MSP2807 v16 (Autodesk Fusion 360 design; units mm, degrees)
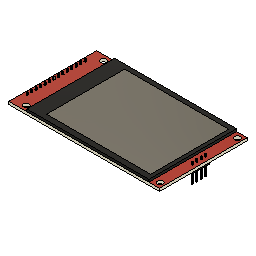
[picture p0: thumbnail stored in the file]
sketch "スケッチ1" plane through (0, 0, 0) normal (0, 1, 0) x axis (1, 0, 0)
  line L1 (85.8, 0) -> (0, 0)
  line L2 (85.8, -50) -> (85.8, 0)
  line L3 (0, -50) -> (85.8, -50)
  line L4 (0, 0) -> (0, -50)
  line L5 (2, 0) -> (0, 0)
  line L6 (2, -50) -> (2, 0)
  line L7 (0, -50) -> (2, -50)
  line L8 (0, 0) -> (0, -50)
  line L9 (2, 0) -> (0, 0)
  line L10 (2, -8.49) -> (2, 0)
  line L11 (0, -8.49) -> (2, -8.49)
  line L12 (0, 0) -> (0, -8.49)
  line L13 (0, -11.03) -> (2, -11.03)
  line L14 (0, -13.57) -> (2, -13.57)
  line L15 (0, -16.11) -> (2, -16.11)
  line L16 (0, -18.65) -> (2, -18.65)
  line L17 (0, -28.81) -> (2, -28.81)
  line L18 (0, -26.27) -> (2, -26.27)
  line L19 (0, -23.73) -> (2, -23.73)
  line L20 (0, -21.19) -> (2, -21.19)
  line L21 (0, -31.35) -> (2, -31.35)
  line L22 (0, -33.89) -> (2, -33.89)
  line L23 (0, -36.43) -> (2, -36.43)
  line L24 (0, -38.97) -> (2, -38.97)
  line L25 (0, -41.51) -> (2, -41.51)
  line L26 (10.3, 0) -> (2, 0)
  line L27 (10.3, -50) -> (10.3, 0)
  line L28 (2, -50) -> (10.3, -50)
  line L29 (2, 0) -> (2, -50)
  line L30 (79.8, 0) -> (2, 0)
  line L31 (79.8, -50) -> (79.8, 0)
  line L32 (2, -50) -> (79.8, -50)
  line L33 (2, 0) -> (2, -50)
  line L34 (18.5, 0) -> (2, 0)
  line L35 (18.5, -2.5) -> (18.5, 0)
  line L36 (2, -2.5) -> (18.5, -2.5)
  line L37 (2, 0) -> (2, -2.5)
  line L38 (77.8, 0) -> (2, 0)
  line L39 (77.8, -46.99) -> (77.8, 0)
  line L40 (2, -46.99) -> (77.8, -46.99)
  line L41 (2, 0) -> (2, -46.99)
  line L42 (77.8, -2.5) -> (18.5, -2.5)
  line L43 (77.8, -46.99) -> (77.8, -2.5)
  line L44 (18.5, -46.99) -> (77.8, -46.99)
  line L45 (18.5, -2.5) -> (18.5, -46.99)
  line L46 (83.28, 0) -> (2, 0)
  line L47 (83.28, -21.19) -> (83.28, 0)
  line L48 (2, -21.19) -> (83.28, -21.19)
  line L49 (2, 0) -> (2, -21.19)
  line L50 (81.28, -21.19) -> (83.28, -21.19)
  line L51 (81.28, -23.73) -> (83.28, -23.73)
  line L52 (81.28, -26.27) -> (83.28, -26.27)
  line L53 (81.28, -28.81) -> (83.28, -28.81)
  line L54 (7, 0) -> (0, 0)
  line L55 (7, -3) -> (7, 0)
  line L56 (0, -3) -> (7, -3)
  line L57 (0, 0) -> (0, -3)
  line L58 (7, -50) -> (0, -50)
  line L59 (7, -47) -> (7, -50)
  line L60 (0, -47) -> (7, -47)
  line L61 (0, -50) -> (0, -47)
  line L62 (83.3, -47) -> (7, -47)
  line L63 (83.3, -3) -> (7, -3)
  line L64 (83.3, 0) -> (83.3, -3)
  line L65 (7, 0) -> (83.3, 0)
  line L66 (7, -3) -> (7, 0)
  line L67 (1.7, -8.49) -> (2, -8.49)
  line L68 (1.7, -8.19) -> (1.7, -8.49)
  line L69 (2, -8.19) -> (1.7, -8.19)
  line L70 (2, -8.49) -> (2, -8.19)
  line L71 (2.3, -8.19) -> (1.7, -8.19)
  line L72 (2.3, -8.79) -> (2.3, -8.19)
  line L73 (1.7, -8.79) -> (2.3, -8.79)
  line L74 (1.7, -8.19) -> (1.7, -8.79)
  line L75 (2.3, -10.73) -> (1.7, -10.73)
  line L76 (2.3, -11.33) -> (2.3, -10.73)
  line L77 (1.7, -11.33) -> (2.3, -11.33)
  line L78 (1.7, -10.73) -> (1.7, -11.33)
  line L79 (2.3, -13.27) -> (1.7, -13.27)
  line L80 (2.3, -13.87) -> (2.3, -13.27)
  line L81 (1.7, -13.27) -> (1.7, -13.87)
  line L82 (1.7, -13.87) -> (2.3, -13.87)
  line L83 (2.3, -15.81) -> (1.7, -15.81)
  line L84 (1.7, -15.81) -> (1.7, -16.41)
  line L85 (1.7, -16.41) -> (2.3, -16.41)
  line L86 (2.3, -16.41) -> (2.3, -15.81)
  line L87 (2, -18.35) -> (1.7, -18.35)
  line L88 (2.3, -18.35) -> (1.7, -18.35)
  line L89 (2.3, -18.95) -> (2.3, -18.35)
  line L90 (1.7, -18.95) -> (2.3, -18.95)
  line L91 (1.7, -18.35) -> (1.7, -18.95)
  line L92 (2.3, -20.89) -> (1.7, -20.89)
  line L93 (1.7, -20.89) -> (1.7, -21.49)
  line L94 (1.7, -21.49) -> (2.3, -21.49)
  line L95 (2.3, -21.49) -> (2.3, -20.89)
  line L96 (2.3, -23.43) -> (1.7, -23.43)
  line L97 (2.3, -24.03) -> (2.3, -23.43)
  line L98 (1.7, -24.03) -> (2.3, -24.03)
  line L99 (1.7, -23.43) -> (1.7, -24.03)
  line L100 (2.3, -26.57) -> (2.3, -25.97)
  line L101 (2.3, -25.97) -> (1.7, -25.97)
  line L102 (1.7, -25.97) -> (1.7, -26.57)
  line L103 (1.7, -26.57) -> (2.3, -26.57)
  line L104 (1.7, -41.81) -> (2.3, -41.81)
  line L105 (1.7, -41.21) -> (1.7, -41.81)
  line L106 (2.3, -41.21) -> (1.7, -41.21)
  line L107 (2.3, -41.81) -> (2.3, -41.21)
  line L108 (1.7, -39.27) -> (2.3, -39.27)
  line L109 (2.3, -39.27) -> (2.3, -38.67)
  line L110 (2.3, -38.67) -> (1.7, -38.67)
  line L111 (1.7, -38.67) -> (1.7, -39.27)
  line L112 (1.7, -36.73) -> (2.3, -36.73)
  line L113 (2.3, -36.73) -> (2.3, -36.13)
  line L114 (2.3, -36.13) -> (1.7, -36.13)
  line L115 (1.7, -36.13) -> (1.7, -36.73)
  line L116 (1.7, -34.19) -> (2.3, -34.19)
  line L117 (1.7, -33.59) -> (1.7, -34.19)
  line L118 (2.3, -34.19) -> (2.3, -33.59)
  line L119 (2.3, -33.59) -> (1.7, -33.59)
  line L120 (2.3, -31.05) -> (1.7, -31.05)
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  point P1 (0, 0)
  point P2 (0, 0)
  point P8 (2, -50)
  point P6 (0, 0)
  point P10 (0, 0)
  point P12 (2, -8.49)
  point P14 (2, -8.49)
  point P83 (0, 0)
  point P88 (7, -47)
  point P90 (7, -47)
  point P85 (7, -3)
  point P91 (7, -3)
  point P92 (7, -47)
  point P93 (83.3, -47)
  point P94 (83.3, -47)
  point P95 (7, -3)
  point P96 (83.3, -3)
  point P99 (83.3, -3)
  point P100 (2, -8.49)
  point P3 (85.8, 0)
  point P5 (0, -50)
  point P7 (2, 0)
  point P11 (2, 0)
  point P13 (0, -8.49)
  point P54 (10.3, 0)
  point P57 (79.8, 0)
  point P60 (18.5, 0)
  point P62 (2, -2.5)
  point P63 (77.8, 0)
  point P65 (2, -46.99)
  point P68 (83.28, 0)
  point P70 (2, -21.19)
  point P84 (7, 0)
  point P86 (0, -3)
  point P87 (7, -50)
  point P89 (0, -47)
  point P101 (1.7, -8.49)
  point P103 (2, -8.19)
  point P102 (1.7, -8.19)
  point P104 (2.3, -8.19)
  point P106 (1.7, -8.79)
  point P108 (2.3, -10.73)
  point P110 (1.7, -10.73)
  point P107 (1.7, -11.33)
  point P116 (2.3, -13.27)
  point P118 (1.7, -13.27)
  point P113 (1.7, -13.87)
  point P111 (1.7, -15.81)
  point P115 (2.3, -15.81)
  point P114 (1.7, -16.41)
  point P126 (2.3, -18.35)
  point P135 (1.7, -18.35)
  point P123 (1.7, -18.95)
  point P119 (1.7, -20.89)
  point P125 (2.3, -20.89)
  point P124 (1.7, -21.49)
  point P122 (1.7, -23.43)
  point P133 (2.3, -23.43)
  point P131 (1.7, -24.03)
  point P128 (1.7, -25.97)
  point P132 (2.3, -25.97)
  point P130 (1.7, -26.57)
  point P137 (1.7, -28.51)
  point P143 (2.3, -28.51)
  point P141 (1.7, -29.11)
  point P138 (1.7, -31.05)
  point P142 (2.3, -31.05)
  point P140 (1.7, -31.65)
  point P146 (1.7, -33.59)
  point P150 (2.3, -33.59)
  point P158 (1.7, -34.19)
  point P147 (2.3, -36.13)
  point P159 (1.7, -36.13)
  point P149 (1.7, -36.73)
  point P145 (2.3, -38.67)
  point P148 (1.7, -38.67)
  point P153 (1.7, -39.27)
  point P144 (2.3, -41.21)
  point P156 (1.7, -41.21)
  point P152 (1.7, -41.81)
  point P166 (83.58, -20.89)
  point P175 (82.98, -20.89)
  point P168 (82.98, -21.49)
  point P165 (83.58, -23.43)
  point P167 (82.98, -23.43)
  point P170 (82.98, -24.03)
  point P164 (83.58, -25.97)
  point P173 (82.98, -25.97)
  point P169 (82.98, -26.57)
  point P160 (82.98, -28.51)
  point P161 (83.58, -28.51)
  point P163 (82.98, -29.11)
  horizontal L1
  vertical L2
  horizontal L3
  vertical L4
  coincident P1 P2
  horizontal L5
  vertical L6
  horizontal L7
  vertical L8
  coincident L3 P8
  coincident P1 P6
  horizontal L9
  vertical L10
  horizontal L11
  vertical L12
  coincident P1 P10
  coincident P12 P14
  horizontal L13
  horizontal L14
  horizontal L15
  horizontal L16
  horizontal L20
  horizontal L19
  horizontal L18
  horizontal L17
  horizontal L21
  horizontal L22
  horizontal L23
  horizontal L24
  horizontal L25
  horizontal L26
  vertical L27
  horizontal L28
  vertical L29
  horizontal L30
  vertical L31
  horizontal L32
  vertical L33
  horizontal L34
  vertical L35
  horizontal L36
  vertical L37
  horizontal L38
  vertical L39
  horizontal L40
  vertical L41
  horizontal L42
  vertical L43
  horizontal L44
  vertical L45
  horizontal L46
  vertical L47
  horizontal L48
  vertical L49
  horizontal L50
  horizontal L51
  horizontal L52
  horizontal L53
  horizontal L54
  vertical L55
  horizontal L56
  vertical L57
  coincident P1 P83
  horizontal L58
  vertical L59
  horizontal L60
  vertical L61
  coincident P88 P90
  coincident P85 P91
  horizontal L62
  coincident P90 P92
  coincident P93 P94
  horizontal L63
  vertical L64
  horizontal L65
  vertical L66
  coincident P91 P95
  coincident P96 P99
  horizontal L67
  vertical L68
  horizontal L69
  vertical L70
  coincident P14 P100
  horizontal L71
  vertical L72
  horizontal L73
  vertical L74
  horizontal L75
  vertical L76
  horizontal L77
  vertical L78
  horizontal L79
  vertical L80
  horizontal L82
  vertical L81
  horizontal L83
  vertical L86
  horizontal L85
  vertical L84
  horizontal L87
  horizontal L88
  vertical L89
  horizontal L90
  vertical L91
  horizontal L92
  vertical L95
  horizontal L94
  vertical L93
  horizontal L96
  vertical L97
  horizontal L98
  vertical L99
  horizontal L101
  vertical L100
  horizontal L103
  vertical L102
  horizontal L120
  horizontal L119
  vertical L118
  horizontal L116
  vertical L117
  horizontal L114
  vertical L113
  horizontal L112
  vertical L115
  horizontal L110
  vertical L109
  horizontal L108
  vertical L111
  horizontal L106
  vertical L107
  horizontal L104
  vertical L105
  dimension "d1" distance P2 P3 = 85.8
  dimension "d2" distance P2 P5 = 50
  dimension "d3" distance P6 P7 = 2
  dimension "d4" distance P10 P11 = 2
  dimension "d5" distance P10 P13 = 8.49
  dimension "d6" diameter = 1
  dimension "d7" diameter = 1
  dimension "d8" diameter = 1
  dimension "d9" diameter = 1
  dimension "d10" diameter = 1
  dimension "d11" diameter = 1
  dimension "d12" diameter = 1
  dimension "d13" diameter = 1
  dimension "d14" diameter = 1
  dimension "d15" diameter = 1
  dimension "d16" diameter = 1
  dimension "d17" diameter = 1
  dimension "d18" diameter = 1
  dimension "d19" diameter = 1
  dimension "d20" distance P7 P54 = 8.3
  dimension "d21" distance P7 P57 = 77.8
  dimension "d22" distance P7 P60 = 16.5
  dimension "d23" distance P7 P62 = 2.5
  dimension "d24" distance P7 P63 = 75.8
  dimension "d25" distance P7 P65 = 46.99
  dimension "d30" distance P7 P68 = 81.28
  dimension "d31" distance P7 P70 = 21.19
  dimension "d32" diameter = 1
  dimension "d33" diameter = 1
  dimension "d34" diameter = 1
  dimension "d35" diameter = 1
  dimension "d36" distance P83 P84 = 7
  dimension "d37" distance P83 P86 = 3
  dimension "d38" distance P5 P87 = 7
  dimension "d39" distance P5 P89 = 3
  dimension "d40" diameter = 3.2
  dimension "d41" diameter = 3.2
  dimension "d42" distance P92 P93 = 76.3 (= "73.1 mm + 3.2 mm")
  dimension "d44" diameter = 3.2
  dimension "d45" distance P95 P96 = 76.3
  dimension "d46" diameter = 3.2
  dimension "d49" distance P100 P101 = 0.3
  dimension "d50" distance P100 P103 = 0.3
  dimension "d51" distance P102 P104 = 0.6
  dimension "d52" distance P102 P106 = 0.6
  dimension "d53" distance P108 P110 = 0.6
  dimension "d54" distance P107 P110 = 0.6
  dimension "d55" distance P116 P118 = 0.6
  dimension "d56" distance P113 P118 = 0.6
  dimension "d57" distance P111 P115 = 0.6
  dimension "d58" distance P111 P114 = 0.6
  dimension "d59" distance P126 P135 = 0.6
  dimension "d60" distance P123 P135 = 0.6
  dimension "d61" distance P119 P125 = 0.6
  dimension "d62" distance P119 P124 = 0.6
  dimension "d63" distance P122 P133 = 0.6
  dimension "d64" distance P122 P131 = 0.6
  dimension "d65" distance P128 P132 = 0.6
  dimension "d66" distance P128 P130 = 0.6
  dimension "d67" distance P137 P143 = 0.6
  dimension "d68" distance P137 P141 = 0.6
  dimension "d69" distance P138 P142 = 0.6
  dimension "d70" distance P138 P140 = 0.6
  dimension "d71" distance P146 P150 = 0.6
  dimension "d72" distance P146 P158 = 0.6
  dimension "d73" distance P147 P159 = 0.6
  dimension "d74" distance P149 P159 = 0.6
  dimension "d75" distance P145 P148 = 0.6
  dimension "d76" distance P148 P153 = 0.6
  dimension "d77" distance P144 P156 = 0.6
  dimension "d78" distance P152 P156 = 0.6
  dimension "d79" distance P166 P175 = 0.6
  dimension "d80" distance P168 P175 = 0.6
  dimension "d81" distance P165 P167 = 0.6
  dimension "d82" distance P167 P170 = 0.6
  dimension "d83" distance P164 P173 = 0.6
  dimension "d84" distance P169 P173 = 0.6
  dimension "d85" distance P160 P161 = 0.6
  dimension "d86" distance P160 P163 = 0.6
extrude "押し出し1" new body sketch "スケッチ1" profile of L39 L40 L42 L43 L44 L45 along normal blind 1.4
sketch "スケッチ2" plane through (0, 0, 0) normal (0, 1, 0) x axis (1, 0, 0)
extrude "押し出し2" new body sketch "スケッチ1" profile of L1 L3 L27 L30 L31 L32 L34 L35 L36 L38 L39 L40 L42 L43 L44 L45 along normal blind 1.4
extrude "押し出し3" new body sketch "スケッチ1" against normal blind 1.6
extrude "押し出し4" new body sketch "スケッチ1" against normal blind 9.8
extrude "押し出し5" add of existing geometry blind 1.4
sketch "スケッチ3" plane through (0, -1.6, 0) normal (0, -1, 0) x axis (1, 0, 0)
  line L1 (85.8, 0) -> (0, 0)
  line L2 (85.8, 50) -> (85.8, 0)
  line L3 (0, 50) -> (85.8, 50)
  line L4 (0, 0) -> (0, 50)
  line L5 (3.24, 41.81) -> (2.3, 41.81)
  line L6 (3.24, 42.75) -> (3.24, 41.81)
  line L7 (2.3, 42.75) -> (3.24, 42.75)
  line L8 (2.3, 41.81) -> (2.3, 42.75)
  line L9 (0.76, 41.81) -> (1.7, 41.81)
  line L10 (0.76, 42.75) -> (0.76, 41.81)
  line L11 (1.7, 42.75) -> (0.76, 42.75)
  line L12 (1.7, 41.81) -> (1.7, 42.75)
  line L13 (0.76, 8.19) -> (1.7, 8.19)
  line L14 (0.76, 7.25) -> (0.76, 8.19)
  line L15 (1.7, 7.25) -> (0.76, 7.25)
  line L16 (1.7, 8.19) -> (1.7, 7.25)
  line L17 (3.24, 7.25) -> (0.76, 7.25)
  line L18 (3.24, 42.75) -> (3.24, 7.25)
  line L19 (0.76, 42.75) -> (3.24, 42.75)
  line L20 (0.76, 7.25) -> (0.76, 42.75)
  line L21 (2.3, 41.81) -> (1.7, 41.81)
  line L22 (2.3, 41.21) -> (2.3, 41.81)
  line L23 (1.7, 41.21) -> (2.3, 41.21)
  line L24 (1.7, 41.81) -> (1.7, 41.21)
  line L25 (84.52, 29.11) -> (83.58, 29.11)
  line L26 (84.52, 30.05) -> (84.52, 29.11)
  line L27 (83.58, 30.05) -> (84.52, 30.05)
  line L28 (83.58, 29.11) -> (83.58, 30.05)
  line L29 (82.04, 20.89) -> (82.98, 20.89)
  line L30 (82.04, 19.95) -> (82.04, 20.89)
  line L31 (82.98, 19.95) -> (82.04, 19.95)
  line L32 (82.98, 20.89) -> (82.98, 19.95)
  line L33 (84.52, 19.95) -> (82.04, 19.95)
  line L34 (84.52, 30.05) -> (84.52, 19.95)
  line L35 (82.04, 30.05) -> (84.52, 30.05)
  line L36 (82.04, 19.95) -> (82.04, 30.05)
  line L37 (2.3, 39.27) -> (1.7, 39.27)
  line L38 (2.3, 38.67) -> (2.3, 39.27)
  line L39 (1.7, 38.67) -> (2.3, 38.67)
  line L40 (1.7, 39.27) -> (1.7, 38.67)
  line L41 (2.3, 36.73) -> (1.7, 36.73)
  line L42 (2.3, 36.13) -> (2.3, 36.73)
  line L43 (1.7, 36.13) -> (2.3, 36.13)
  line L44 (1.7, 36.73) -> (1.7, 36.13)
  line L45 (2.3, 34.19) -> (1.7, 34.19)
  line L46 (2.3, 33.59) -> (2.3, 34.19)
  line L47 (1.7, 33.59) -> (2.3, 33.59)
  line L48 (1.7, 34.19) -> (1.7, 33.59)
  line L49 (2.3, 31.65) -> (1.7, 31.65)
  line L50 (2.3, 31.05) -> (2.3, 31.65)
  line L51 (1.7, 31.05) -> (2.3, 31.05)
  line L52 (1.7, 31.65) -> (1.7, 31.05)
  line L53 (2.3, 29.11) -> (1.7, 29.11)
  line L54 (2.3, 28.51) -> (2.3, 29.11)
  line L55 (1.7, 28.51) -> (2.3, 28.51)
  line L56 (1.7, 29.11) -> (1.7, 28.51)
  line L57 (2.3, 26.57) -> (1.7, 26.57)
  line L58 (2.3, 25.97) -> (2.3, 26.57)
  line L59 (1.7, 25.97) -> (2.3, 25.97)
  line L60 (1.7, 26.57) -> (1.7, 25.97)
  line L61 (2.3, 24.03) -> (1.7, 24.03)
  line L62 (2.3, 23.43) -> (2.3, 24.03)
  line L63 (1.7, 23.43) -> (2.3, 23.43)
  line L64 (1.7, 24.03) -> (1.7, 23.43)
  line L65 (2.3, 21.49) -> (1.7, 21.49)
  line L66 (2.3, 20.89) -> (2.3, 21.49)
  line L67 (1.7, 20.89) -> (2.3, 20.89)
  line L68 (1.7, 21.49) -> (1.7, 20.89)
  line L69 (2.3, 18.95) -> (1.7, 18.95)
  line L70 (2.3, 18.35) -> (2.3, 18.95)
  line L71 (1.7, 18.35) -> (2.3, 18.35)
  line L72 (1.7, 18.95) -> (1.7, 18.35)
  line L73 (2.3, 16.41) -> (1.7, 16.41)
  line L74 (2.3, 15.81) -> (2.3, 16.41)
  line L75 (1.7, 15.81) -> (2.3, 15.81)
  line L76 (1.7, 16.41) -> (1.7, 15.81)
  line L77 (2.3, 13.87) -> (1.7, 13.87)
  line L78 (2.3, 13.27) -> (2.3, 13.87)
  line L79 (1.7, 13.27) -> (2.3, 13.27)
  line L80 (1.7, 13.87) -> (1.7, 13.27)
  line L81 (2.3, 11.33) -> (1.7, 11.33)
  line L82 (2.3, 10.73) -> (2.3, 11.33)
  line L83 (1.7, 10.73) -> (2.3, 10.73)
  line L84 (1.7, 11.33) -> (1.7, 10.73)
  line L85 (2.3, 8.79) -> (1.7, 8.79)
  line L86 (2.3, 8.19) -> (2.3, 8.79)
  line L87 (1.7, 8.19) -> (2.3, 8.19)
  line L88 (1.7, 8.79) -> (1.7, 8.19)
  line L89 (83.58, 29.11) -> (82.98, 29.11)
  line L90 (83.58, 28.51) -> (83.58, 29.11)
  line L91 (82.98, 28.51) -> (83.58, 28.51)
  line L92 (82.98, 29.11) -> (82.98, 28.51)
  line L93 (83.58, 26.57) -> (82.98, 26.57)
  line L94 (83.58, 25.97) -> (83.58, 26.57)
  line L95 (82.98, 25.97) -> (83.58, 25.97)
  line L96 (82.98, 26.57) -> (82.98, 25.97)
  line L97 (83.58, 24.03) -> (82.98, 24.03)
  line L98 (83.58, 23.43) -> (83.58, 24.03)
  line L99 (82.98, 23.43) -> (83.58, 23.43)
  line L100 (82.98, 24.03) -> (82.98, 23.43)
  line L101 (83.58, 21.49) -> (82.98, 21.49)
  line L102 (83.58, 20.89) -> (83.58, 21.49)
  line L103 (82.98, 20.89) -> (83.58, 20.89)
  line L104 (82.98, 21.49) -> (82.98, 20.89)
  line L105 (25.87, 50) -> (0, 50)
  line L106 (25.87, 48.7) -> (25.87, 50)
  line L107 (0, 48.7) -> (25.87, 48.7)
  line L108 (0, 50) -> (0, 48.7)
  line L109 (52.52, 48.7) -> (25.87, 48.7)
  line L110 (52.52, 31.16) -> (52.52, 48.7)
  line L111 (25.87, 31.16) -> (52.52, 31.16)
  line L112 (25.87, 48.7) -> (25.87, 31.16)
  line L113 (28.07, 48.7) -> (25.87, 48.7)
  line L114 (28.07, 39.7) -> (28.07, 48.7)
  line L115 (25.87, 39.7) -> (28.07, 39.7)
  line L116 (25.87, 48.7) -> (25.87, 39.7)
  line L117 (28.07, 39.7) -> (25.87, 39.7)
  line L118 (28.07, 37.7) -> (28.07, 39.7)
  line L119 (25.87, 37.7) -> (28.07, 37.7)
  line L120 (25.87, 39.7) -> (25.87, 37.7)
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  point P27 (0, 50)
  point P123 (0, 50)
  point P26 (85.8, 50)
  point P164 (85.8, 50)
  point P25 (85.8, 0)
  point P195 (85.8, 0)
  point P28 (2.3, 41.81)
  point P29 (3.24, 41.81)
  point P31 (2.3, 42.75)
  point P32 (1.7, 41.81)
  point P33 (0.76, 41.81)
  point P35 (1.7, 42.75)
  point P36 (1.7, 8.19)
  point P37 (0.76, 8.19)
  point P39 (1.7, 7.25)
  point P42 (2.3, 41.81)
  point P44 (1.7, 41.21)
  point P45 (83.58, 29.11)
  point P46 (84.52, 29.11)
  point P48 (83.58, 30.05)
  point P49 (82.98, 20.89)
  point P50 (82.04, 20.89)
  point P52 (82.98, 19.95)
  point P124 (25.87, 50)
  point P126 (0, 48.7)
  point P125 (25.87, 48.7)
  point P127 (52.52, 48.7)
  point P129 (25.87, 31.16)
  point P130 (28.07, 48.7)
  point P132 (25.87, 39.7)
  point P133 (28.07, 39.7)
  point P135 (25.87, 37.7)
  point P128 (52.52, 31.16)
  point P146 (37.02, 31.16)
  point P148 (52.52, 22.66)
  point P147 (37.02, 22.66)
  point P149 (39.02, 22.66)
  point P152 (41.02, 22.66)
  point P155 (37.82, 22.66)
  point P157 (37.02, 21.06)
  point P158 (39.82, 22.66)
  point P160 (39.02, 21.06)
  point P161 (41.82, 22.66)
  point P163 (41.02, 21.06)
  point P165 (62.3, 50)
  point P167 (85.8, 29.5)
  point P168 (69.8, 50)
  point P166 (62.3, 29.5)
  point P171 (63.1, 29.5)
  point P173 (62.3, 27.9)
  point P169 (69.8, 29.5)
  point P174 (70.6, 29.5)
  point P176 (69.8, 27.9)
  point P177 (65.8, 50)
  point P178 (65.8, 29.5)
  point P180 (67.2, 29.5)
  point P182 (65.8, 26.5)
  point P183 (62.3, 50)
  point P185 (85.8, 21)
  point P184 (62.3, 21)
  point P186 (63.1, 21)
  point P188 (62.3, 22.6)
  point P189 (64.8, 21)
  point P191 (63.1, 22.4)
  point P192 (67.8, 21)
  point P194 (64.8, 22.7)
  point P196 (59.8, 0)
  point P198 (85.8, 17)
  point P197 (59.8, 17)
  point P199 (64.1, 17)
  point P201 (59.8, 11.9)
  point P202 (67.8, 0)
  point P204 (85.8, 12.5)
  point P203 (67.8, 12.5)
  point P205 (68.6, 12.5)
  point P207 (67.8, 10.9)
  point P208 (69.3, 0)
  point P209 (69.3, 12.5)
  point P211 (70.1, 12.5)
  point P213 (69.3, 10.9)
  point P214 (42.9, 50)
  point P216 (0, 25)
  horizontal L5
  vertical L6
  horizontal L7
  vertical L8
  horizontal L9
  vertical L10
  horizontal L11
  vertical L12
  horizontal L13
  vertical L14
  horizontal L15
  vertical L16
  horizontal L17
  vertical L18
  horizontal L19
  vertical L20
  horizontal L21
  vertical L22
  horizontal L23
  vertical L24
  horizontal L25
  vertical L26
  horizontal L27
  vertical L28
  horizontal L29
  vertical L30
  horizontal L31
  vertical L32
  horizontal L33
  vertical L34
  horizontal L35
  vertical L36
  horizontal L37
  vertical L38
  horizontal L39
  vertical L40
  horizontal L41
  vertical L42
  horizontal L43
  vertical L44
  horizontal L45
  vertical L46
  horizontal L47
  vertical L48
  horizontal L49
  vertical L50
  horizontal L51
  vertical L52
  horizontal L53
  vertical L54
  horizontal L55
  vertical L56
  horizontal L57
  vertical L58
  horizontal L59
  vertical L60
  horizontal L61
  vertical L62
  horizontal L63
  vertical L64
  horizontal L65
  vertical L66
  horizontal L67
  vertical L68
  horizontal L69
  vertical L70
  horizontal L71
  vertical L72
  horizontal L73
  vertical L74
  horizontal L75
  vertical L76
  horizontal L77
  vertical L78
  horizontal L79
  vertical L80
  horizontal L81
  vertical L82
  horizontal L83
  vertical L84
  horizontal L85
  vertical L86
  horizontal L87
  vertical L88
  horizontal L89
  vertical L90
  horizontal L91
  vertical L92
  horizontal L93
  vertical L94
  horizontal L95
  vertical L96
  horizontal L97
  vertical L98
  horizontal L99
  vertical L100
  horizontal L101
  vertical L102
  horizontal L103
  vertical L104
  horizontal L105
  vertical L106
  horizontal L107
  vertical L108
  coincident P27 P123
  horizontal L109
  vertical L110
  horizontal L111
  vertical L112
  horizontal L113
  vertical L114
  horizontal L115
  vertical L116
  horizontal L117
  vertical L118
  horizontal L119
  vertical L120
  coincident P26 P164
  coincident P25 P195
  dimension "d91" distance P28 P29 = 0.94
  dimension "d92" distance P28 P31 = 0.94
  dimension "d93" distance P32 P33 = 0.94
  dimension "d94" distance P32 P35 = 0.94
  dimension "d95" distance P36 P37 = 0.94
  dimension "d96" distance P36 P39 = 0.94
  dimension "d97" distance P32 P42 = 0.6
  dimension "d98" distance P32 P44 = 0.6
  dimension "d99" distance P45 P46 = 0.94
  dimension "d100" distance P45 P48 = 0.94
  dimension "d101" distance P49 P50 = 0.94
  dimension "d102" distance P49 P52 = 0.94
  dimension "d105" distance P123 P124 = 25.87
  dimension "d106" distance P123 P126 = 1.3
  dimension "d107" distance P125 P127 = 26.65
  dimension "d108" distance P125 P129 = 17.54
  dimension "d109" distance P125 P130 = 2.2
  dimension "d110" distance P125 P132 = 9
  dimension "d111" distance P132 P133 = 2.2
  dimension "d112" distance P132 P135 = 2
  dimension "d124" distance P128 P146 = 15.5
  dimension "d125" distance P128 P148 = 8.5
  dimension "d126" distance P147 P149 = 2
  dimension "d127" distance P149 P152 = 2
  dimension "d128" distance P147 P155 = 0.8
  dimension "d129" distance P147 P157 = 1.6
  dimension "d130" distance P149 P158 = 0.8
  dimension "d131" distance P149 P160 = 1.6
  dimension "d132" distance P152 P161 = 0.8
  dimension "d133" distance P152 P163 = 1.6
  dimension "d134" distance P164 P165 = 23.5
  dimension "d135" distance P164 P167 = 20.5
  dimension "d136" distance P164 P168 = 16
  dimension "d137" distance P166 P171 = 0.8
  dimension "d138" distance P166 P173 = 1.6
  dimension "d139" distance P169 P174 = 0.8
  dimension "d140" distance P169 P176 = 1.6
  dimension "d141" distance P164 P177 = 20
  dimension "d142" distance P178 P180 = 1.4
  dimension "d143" distance P178 P182 = 3
  dimension "d144" distance P164 P183 = 23.5
  dimension "d145" distance P164 P185 = 29
  dimension "d146" distance P184 P186 = 0.8
  dimension "d147" distance P184 P188 = 1.6
  dimension "d148" distance P186 P189 = 1.7
  dimension "d149" distance P186 P191 = 1.4
  dimension "d150" distance P189 P192 = 3
  dimension "d151" distance P189 P194 = 1.7
  dimension "d152" distance P195 P196 = 26
  dimension "d153" distance P195 P198 = 17
  dimension "d154" distance P197 P199 = 4.3
  dimension "d155" distance P197 P201 = 5.1
  dimension "d156" distance P195 P202 = 18
  dimension "d157" distance P195 P204 = 12.5
  dimension "d158" distance P203 P205 = 0.8
  dimension "d159" distance P203 P207 = 1.6
  dimension "d160" distance P195 P208 = 16.5
  dimension "d161" distance P209 P211 = 0.8
  dimension "d162" distance P209 P213 = 1.6
  dimension "d174" distance P123 P214 = 42.9 (= "( 85.8 / 2 ) * 1 mm")
  dimension "d175" distance P123 P216 = 25
  dimension "d167" Text1-Height = 2.5
extrude "押し出し6" new body sketch "スケッチ3" along normal blind 2
extrude "押し出し7" new body sketch "スケッチ3" along normal blind 3
extrude "押し出し8" new body sketch "スケッチ3" along normal blind 3
extrude "押し出し9" cut of existing geometry blind -2.7
extrude "押し出し10" add of existing geometry blind 0.1
extrude "押し出し11" cut of existing geometry blind -0.1
extrude "押し出し12" new body sketch "スケッチ3" along normal blind 0.5
extrude "押し出し13" new body sketch "スケッチ3" along normal blind 1.1
extrude "押し出し14" cut sketch "スケッチ3" against normal blind 0.1
extrude "押し出し15" new body of existing geometry blind 0.1
extrude "押し出し17" new body sketch "スケッチ3" along normal blind 5
move "移動" RotateAngle 180
extrude "押し出し18" add of existing geometry blind 0.1
extrude "押し出し19" cut of existing geometry blind -5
